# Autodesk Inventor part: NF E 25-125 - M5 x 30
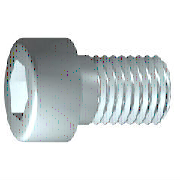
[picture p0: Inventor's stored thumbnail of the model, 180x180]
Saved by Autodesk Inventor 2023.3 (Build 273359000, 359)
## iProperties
Created: 2022-02
Part Number: NF E 25-125 - M5 x 30
Material: Acier, doux
Description: Tête cylindrique fendue - Produit de classe A - Symbole C S
Document SubType Name: Modeling
Standard: NF E 25-125
Designer: Thier
Standards Organization: AFNOR
Language: fr-FR
Size Designation: M5 x 30
Categories: <MemberInstance><Categories><Category DisplayName="Visserie" InternalName="e4da775c-781d-43d5-af7c-5136215cf5a6" Mnemonic="FSTN"><Category DisplayName="Vis" Int
Density: 7.85 g/cm^3
Appearance: Semi-poli
IsCustomPart: 0
Author: Thier
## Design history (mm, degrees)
sketch "Esquisse1"
  geometry: L1 (-1.167, 0)-(30, 0); L2 (30, 0)-(30, 2.5); L3 (30, 2.5)-(8, 2.5); L4 (8, 2.5)-(7.509, 2.5); L5 (7.509, 2.5)-(0, 2.5); L6 (0, 2.5)-(0, 4.25); L7 (0, 4.25)-(-5, 4.25); L8 (-5, 4.25)-(-5, 2.309); L9 (-5, 2.309)-(-2.5, 2.309); L10 (-2.5, 2.309)-(-1.167, 0); L11 (-12, 0)-(37, 0) reference; L12 (0, -0.85)-(0, 5.1) reference; L13 (8, 2.5)-(0, 2.5)
  constraints: 22 end point, 6 parallel, 2 collinear, 2 perpendicular, 1 horizontal, 1 point on line
  dimensions: "d1" = 22 distance from line of L3.end L2 (= GEL); "d2" = 0.49086 distance of L4.end L3.end (computed from GAL); "d3" = 5 distance between parallel lines of L8 L6 (= KOH); "d4" = 2.5 distance of L8.end L9.end (= INTI); "d5" = 60 deg angle of L10 L1; "d6" = 5 diameter of L3 L1 (= GD); "d7" = 5 diameter of L5 L1 (= BDM); "d8" = 4.6188 diameter of L9 L1 (= 1.1547 x SW); "d9" = 8.5 diameter of L7 L1 (= KOD); "d26" = 30 distance between parallel lines of L12 L2 (= NLG)
revolve "Corps" sketch "Esquisse1" stored, may be unused: angle "d10" = 90 deg
sketch "Esquisse2"
  geometry: L1 (0, -5.95)-(0, 5.95) reference; L2 (-5.95, 0)-(5.95, 0) reference; L3 (2.309, 0)-(1.155, -2); L4 (1.155, -2)-(-1.155, -2); L5 (-1.155, -2)-(-2.309, 0); L6 (-2.309, 0)-(-1.155, 2); L7 (-1.155, 2)-(1.155, 2); L8 (1.155, 2)-(2.309, 0); 2 further points
  constraints: 12 end point, 1 coincident, 1 horizontal alignment, 1 point on line, 12 other
extrude "Rainure" join sketch "Esquisse2" stored distance "d11" = 10; taper "d12" = 0 deg
workplane "Work Plane1"
fillet "Fillet2" dims "d30" = 0.1 (= R)
body "Solid1"
fillet "Congé1" dims "d17" = 0.5 (= RR)
feature "Filetage" dims "d13" = 22 (= GEL), "d14" = 0
chamfer "Chanfrein1" distance "d15" = 0.49076 (= -0.5 x SPD + 0.5 x GD); stored, may be unused: second distance "d16" = 0.49076 (= GUL), angle "d27" = 45 deg
other parameters: "GD" = 5 (= NND) [user parameter; used in 2 equation terms], "NLG" = 30 [user parameter; used in 1 equation term], "GEL" = 22 [user parameter; used in 2 equation terms], "KOD" = 8.5 [user parameter; used in 1 equation term], "KOH" = 5 (= NND) [user parameter; used in 1 equation term], "INTI" = 2.5 [user parameter; used in 1 equation term], "GAL" = 0.49076 (= 0.61345 x PTC) [user parameter; used in 1 equation term], "GUL" = 0.49076 (= 0.61345 x PTC) [user parameter; used in 1 equation term], "BDM" = 5 (= NND) [user parameter; used in 1 equation term], "SW" = 4 [user parameter; used in 2 equation terms], "RR" = 0.5 [user parameter; used in 1 equation term], "SPD" = 4.01848 (= NND - 1.2269 x PTC) [user parameter; used in 1 equation term], "d19" = 0, "d28" = 0, "d29" = 0, "R" = 0.1 [user parameter; used in 1 equation term], "TOA" = 30 deg [user parameter], "GD1" = 4.01848 (= THREADDIA - 1.2269 x PTC) [user parameter], "THREADDIA" = 5 [user parameter; used in 1 equation term], "FAWI" = 45 deg [user parameter], "TPU" = 12.5 (computed from PTC) [user parameter], "PTC" = 0.8 [user parameter; used in 5 equation terms], "NND" = 5 [user parameter; used in 4 equation terms], "E0" = 4.62 (= 1.155 x SW) [user parameter]
